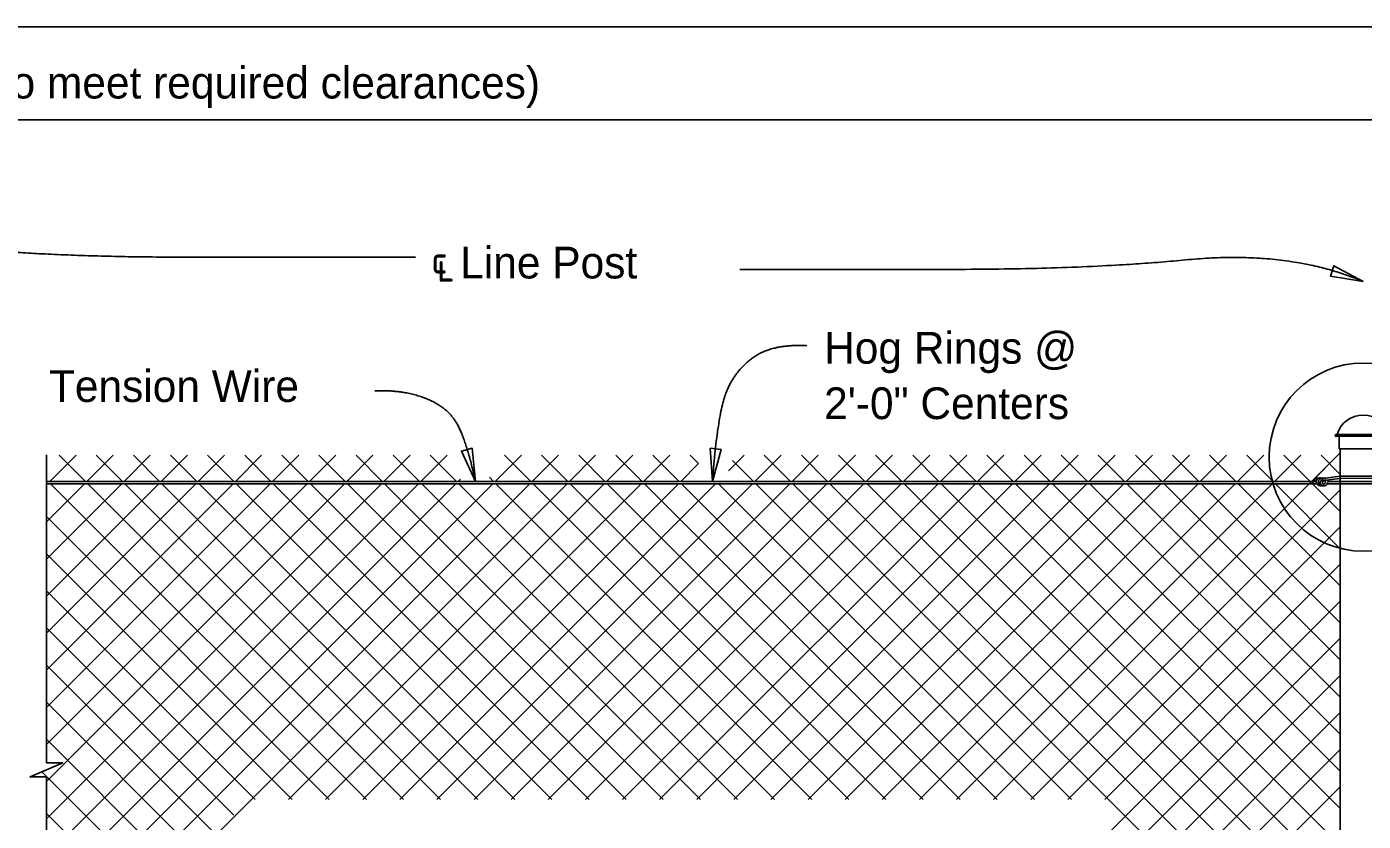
# Model space of a CAD drawing. Extents: x 0 to 41.1, y 0 to 25.9.
# Drawn here: x 16.13 to 24.62, y 20.9 to 25.95 of the extents above; entities that cross this region are included whole.
import ezdxf

# ---------------------------------------------------------------- set-up
doc = ezdxf.new("R2010")
doc.units = 0
for name, color, linetype in [('ActivePts-ConstElements', 7, 'Continuous'), ('Dimension', 7, 'Continuous'), ('Miscellaneous', 7, 'Continuous'), ('Miscellaneous1', 7, 'Continuous'), ('SteelMisc', 7, 'Continuous'), ('SteelMisc_h', 7, 'Continuous'), ('TextStructures', 7, 'Continuous')]:
    doc.layers.add(name, color=color, linetype=linetype)

msp = doc.modelspace()

# ---------------------------------------------------------------- linework, layer by layer
at = {"layer": 'ActivePts-ConstElements'}
msp.add_lwpolyline([(0, 0), (41.0506, 0), (41.0506, 25.9461), (0, 25.9461)], close=True, dxfattribs=at)
at = {"layer": 'Dimension'}
for points in [[(13.615, 25.3556), (15.0787, 25.3556), (15.0787, 25.4589), (15.1237, 25.3556), (15.1687, 25.2523), (15.1687, 25.3556), (28.4596, 25.3556)], [(16.252, 23.2265), (16.252, 21.2702), (16.3553, 21.2702), (16.252, 21.2252), (16.1487, 21.1802), (16.252, 21.1802), (16.252, 20.2867)]]:
    msp.add_lwpolyline(points, dxfattribs=at)
for points in [[(24.6151, 24.3284), (24.4287, 24.4277), (24.4064, 24.3608)], [(18.9764, 23.0579), (18.9562, 23.2681), (18.8881, 23.2497)], [(20.4816, 23.0579), (20.5377, 23.2615), (20.4675, 23.2686)]]:
    msp.add_lwpolyline(points, close=True, dxfattribs=at)
msp.add_circle((24.615, 23.212), 0.5976, dxfattribs=at)
for points in [[(18.5966, 24.4827), (17.7933, 24.4827), (16.4039, 24.4827), (15.2225, 24.5773), (14.615, 24.6814)], [(20.6562, 24.4046), (21.1029, 24.4046), (22.8703, 24.4046), (24.1369, 24.5276), (24.615, 24.3283)], [(21.0813, 23.9198), (20.8634, 23.9322), (20.6196, 23.7577), (20.5135, 23.4738), (20.4817, 23.0578)], [(18.338, 23.6332), (18.5184, 23.6403), (18.8013, 23.5305), (18.9216, 23.311), (18.9764, 23.0578)]]:
    msp.add_open_spline(points, degree=2, dxfattribs=at)
at = {"layer": 'Miscellaneous'}
for p, q in [((16.2736, 23.0578), (16.4402, 23.2245)), ((16.3328, 23.2245), (16.4994, 23.0578)), ((16.5093, 23.0578), (16.6759, 23.2245)), ((16.5685, 23.2245), (16.7352, 23.0578)), ((16.745, 23.0578), (16.9116, 23.2245)), ((16.8042, 23.2245), (16.9709, 23.0578)), ((16.9807, 23.0578), (17.1473, 23.2245)), ((17.0399, 23.2245), (17.2066, 23.0578)), ((17.2164, 23.0578), (17.383, 23.2245)), ((17.2756, 23.2245), (17.4423, 23.0578)), ((17.4521, 23.0578), (17.6187, 23.2245)), ((17.5113, 23.2245), (17.678, 23.0578)), ((17.6878, 23.0578), (17.8544, 23.2245)), ((17.747, 23.2245), (17.9137, 23.0578)), ((17.9235, 23.0578), (18.0901, 23.2245)), ((17.9827, 23.2245), (18.1494, 23.0578)), ((18.1592, 23.0578), (18.3258, 23.2245)), ((18.2184, 23.2245), (18.3851, 23.0578)), ((18.3949, 23.0578), (18.5615, 23.2245)), ((18.4541, 23.2245), (18.6208, 23.0578)), ((18.6306, 23.0578), (18.7972, 23.2245)), ((18.6898, 23.2245), (18.8565, 23.0578)), ((19.102, 23.0578), (19.2687, 23.2245)), ((19.1612, 23.2245), (19.3279, 23.0578)), ((19.3377, 23.0578), (19.5044, 23.2245)), ((19.3969, 23.2245), (19.5636, 23.0578)), ((19.5734, 23.0578), (19.7401, 23.2245)), ((19.6326, 23.2245), (19.7993, 23.0578)), ((19.8091, 23.0578), (19.9758, 23.2245)), ((19.8683, 23.2245), (20.035, 23.0578)), ((20.0448, 23.0578), (20.2115, 23.2245)), ((20.104, 23.2245), (20.2707, 23.0578)), ((20.3397, 23.2245), (20.3934, 23.1708)), ((20.5829, 23.1245), (20.6829, 23.2245)), ((20.6086, 23.1914), (20.7421, 23.0578)), ((20.7519, 23.0578), (20.9186, 23.2245)), ((20.8111, 23.2245), (20.9778, 23.0578)), ((20.9876, 23.0578), (21.1543, 23.2245)), ((21.0468, 23.2245), (21.2135, 23.0578)), ((21.2233, 23.0578), (21.39, 23.2245)), ((21.2825, 23.2245), (21.4492, 23.0578)), ((21.459, 23.0578), (21.6257, 23.2245)), ((21.5182, 23.2245), (21.6849, 23.0578)), ((21.6947, 23.0578), (21.8614, 23.2245)), ((21.7539, 23.2245), (21.9206, 23.0578)), ((21.9304, 23.0578), (22.0971, 23.2245)), ((21.9896, 23.2245), (22.1563, 23.0578)), ((22.1661, 23.0578), (22.3328, 23.2245)), ((22.2253, 23.2245), (22.392, 23.0578)), ((22.2674, 21.0378), (24.4692, 23.2396)), ((22.4018, 23.0578), (22.5685, 23.2245)), ((22.461, 23.2245), (22.6277, 23.0578)), ((22.6375, 23.0578), (22.8042, 23.2245)), ((22.6967, 23.2245), (22.8634, 23.0578)), ((22.8732, 23.0578), (23.0399, 23.2245)), ((22.9324, 23.2245), (23.0991, 23.0578)), ((23.1089, 23.0578), (23.2756, 23.2245)), ((23.1681, 23.2245), (23.3348, 23.0578)), ((23.3446, 23.0578), (23.5113, 23.2245)), ((23.4038, 23.2245), (23.5705, 23.0578)), ((23.5803, 23.0578), (23.747, 23.2245)), ((23.6396, 23.2245), (23.8062, 23.0578)), ((23.816, 23.0578), (23.9827, 23.2245)), ((23.8753, 23.2245), (24.0419, 23.0578)), ((24.0517, 23.0578), (24.2184, 23.2245)), ((24.111, 23.2245), (24.2776, 23.0578)), ((24.2874, 23.0578), (24.4541, 23.2245)), ((24.3467, 23.2245), (24.4692, 23.1019)), ((20.2805, 23.0578), (20.3934, 23.1708)), ((16.252, 19.7364), (19.5586, 23.0431)), ((16.252, 20.2078), (19.0872, 23.0431)), ((16.252, 21.1506), (18.1444, 23.0431)), ((16.252, 20.6792), (18.6158, 23.0431)), ((16.252, 19.9721), (19.3229, 23.0431)), ((16.252, 20.4435), (18.8515, 23.0431)), ((16.252, 20.9149), (18.3801, 23.0431)), ((16.252, 21.3863), (17.9087, 23.0431)), ((16.252, 21.622), (17.673, 23.0431)), ((16.252, 22.0934), (17.2016, 23.0431)), ((16.252, 21.8577), (17.4373, 23.0431)), ((16.252, 22.5648), (16.7302, 23.0431)), ((16.252, 23.0363), (16.2588, 23.0431)), ((16.252, 22.3291), (16.9659, 23.0431)), ((16.252, 22.8005), (16.4945, 23.0431)), ((16.2785, 23.0431), (18.2838, 21.0378)), ((16.5142, 23.0431), (18.5195, 21.0378)), ((16.7499, 23.0431), (18.7552, 21.0378)), ((16.9856, 23.0431), (18.9909, 21.0378)), ((17.2213, 23.0431), (19.2266, 21.0378)), ((17.457, 23.0431), (19.4623, 21.0378)), ((17.6927, 23.0431), (19.698, 21.0378)), ((17.7891, 21.0378), (19.7943, 23.0431)), ((17.9284, 23.0431), (19.9337, 21.0378)), ((18.0248, 21.0378), (20.03, 23.0431)), ((18.1641, 23.0431), (20.1694, 21.0378)), ((18.2605, 21.0378), (20.2657, 23.0431)), ((18.3998, 23.0431), (20.4051, 21.0378)), ((18.4962, 21.0378), (20.5014, 23.0431)), ((18.6355, 23.0431), (20.6408, 21.0378)), ((18.7319, 21.0378), (20.7372, 23.0431)), ((18.8663, 23.0578), (18.8813, 23.0728)), ((18.8712, 23.0431), (20.8765, 21.0378)), ((18.9676, 21.0378), (20.9729, 23.0431)), ((19.065, 23.085), (19.0922, 23.0578)), ((19.1069, 23.0431), (21.1122, 21.0378)), ((19.2033, 21.0378), (21.2086, 23.0431)), ((19.3426, 23.0431), (21.3479, 21.0378)), ((19.439, 21.0378), (21.4443, 23.0431)), ((19.5783, 23.0431), (21.5836, 21.0378)), ((19.6747, 21.0378), (21.68, 23.0431)), ((19.814, 23.0431), (21.8193, 21.0378)), ((19.9104, 21.0378), (21.9157, 23.0431)), ((20.0497, 23.0431), (22.055, 21.0378)), ((20.1461, 21.0378), (22.1514, 23.0431)), ((20.2854, 23.0431), (22.2907, 21.0378)), ((20.3818, 21.0378), (22.3871, 23.0431)), ((20.5211, 23.0431), (22.5264, 21.0378)), ((20.6175, 21.0378), (22.6228, 23.0431)), ((20.7568, 23.0431), (22.7621, 21.0378)), ((20.8532, 21.0378), (22.8585, 23.0431)), ((20.9925, 23.0431), (24.4692, 19.5664)), ((21.0889, 21.0378), (23.0942, 23.0431)), ((21.2282, 23.0431), (24.4692, 19.8021)), ((21.3246, 21.0378), (23.3299, 23.0431)), ((21.4639, 23.0431), (24.4692, 20.0378)), ((21.5603, 21.0378), (23.5656, 23.0431)), ((21.6996, 23.0431), (24.4692, 20.2735)), ((21.796, 21.0378), (23.8013, 23.0431)), ((21.9353, 23.0431), (24.4692, 20.5092)), ((22.0317, 21.0378), (24.037, 23.0431)), ((22.1711, 23.0431), (24.4692, 20.7449)), ((22.4068, 23.0431), (24.4692, 20.9806)), ((22.5031, 21.0378), (24.4692, 23.0039)), ((22.6425, 23.0431), (24.4692, 21.2163)), ((22.8782, 23.0431), (24.4692, 21.452)), ((23.1139, 23.0431), (24.4692, 21.6877)), ((23.3496, 23.0431), (24.4692, 21.9234)), ((23.5853, 23.0431), (24.4692, 22.1591)), ((23.821, 23.0431), (24.4692, 22.3948)), ((24.0567, 23.0431), (24.4692, 22.6305)), ((24.2924, 23.0431), (24.4692, 22.8662)), ((16.252, 22.8339), (18.0481, 21.0378)), ((22.7388, 21.0378), (24.4692, 22.7682)), ((16.252, 22.5982), (17.8124, 21.0378)), ((22.9745, 21.0378), (24.4692, 22.5325)), ((16.252, 22.3625), (17.5767, 21.0378)), ((22.9985, 20.8261), (24.4692, 22.2968)), ((16.252, 22.1268), (17.4417, 20.9371)), ((22.9985, 20.5904), (24.4692, 22.0611)), ((16.252, 21.8911), (17.4417, 20.7014)), ((22.9985, 20.3547), (24.4692, 21.8254)), ((16.252, 21.6554), (17.4417, 20.4657)), ((22.9985, 20.119), (24.4692, 21.5897)), ((16.252, 21.4197), (17.4417, 20.23)), ((21.9677, 18.8525), (24.4692, 21.354)), ((16.2232, 21.2127), (17.4417, 19.9943)), ((22.2034, 18.8525), (24.4692, 21.1183)), ((16.252, 20.9483), (19.7943, 17.4059))]:
    msp.add_line(p, q, dxfattribs=at)
at = {"layer": 'Miscellaneous1'}
msp.add_lwpolyline([(0, 25.9461), (41.0506, 25.9461), (41.0506, 0), (0, 0)], close=True, dxfattribs=at)
at = {"layer": 'SteelMisc'}
for p, q in [((24.4427, 23.3564), (24.7873, 23.3564)), ((24.7873, 23.3442), (24.4427, 23.3442)), ((24.461, 23.2645), (24.461, 23.3442)), ((24.7691, 23.2645), (24.461, 23.2645)), ((24.4692, 16.8894), (24.4692, 23.2644)), ((24.4692, 23.0904), (24.3743, 23.0793)), ((24.4692, 23.0904), (24.7604, 23.0921)), ((16.252, 23.0578), (24.2941, 23.0578)), ((16.252, 23.0431), (24.3207, 23.0431)), ((24.304, 23.0578), (24.3172, 23.0578)), ((24.4692, 23.0759), (24.3766, 23.0664)), ((24.3856, 23.0431), (24.4692, 23.0431)), ((24.387, 23.0578), (24.4692, 23.0578)), ((24.4692, 23.0759), (24.7604, 23.0776))]:
    msp.add_line(p, q, dxfattribs=at)
msp.add_arc((24.4429, 23.3502), 0.00613, 91.1647, 268.8353, dxfattribs=at)
for centre, major_axis, ratio, start_param, end_param in [((24.6157, 23.3154), (0.1711, 0), 0.957868, 0.252602, 2.888574), ((24.3283, 23.0436), (0.0373, 0), 0.957868, 1.486836, 3.108042), ((24.3494, 23.0039), (-0.0724, 0), 0.957868, 5.162149, 5.652106), ((24.3419, 23.0555), (-0.0249, 0), 0.957868, 6.009018, 7.089857), ((24.3408, 23.058), (0.023, 0), 0.957868, 1.29026, 2.970541), ((24.3433, 23.0515), (0.0231, 0), 0.957868, 3.779554, 4.879821), ((24.3595, 23.0527), (0.0295, 0), 0.957868, 1.220941, 4.039556), ((24.373, 23.0544), (-0.0303, -0.0108), 0.724765, 4.35367, 6.324556), ((24.3494, 23.0458), (0.0206, -0.0021), 0.798607, 4.32653, 5.220153), ((24.3629, 23.0458), (0.0206, -0.0021), 0.798607, 3.333154, 5.220153), ((24.3697, 23.0504), (-0.0139, 0), 0.957868, 5.22362, 6.905413), ((24.364, 23.048), (-0.00795, 0), 0.957868, 6.140374, 9.314262), ((24.3781, 23.0415), (-0.0259, 0), 0.957868, 4.777514, 5.62749), ((24.3624, 23.0538), (0.0119, 0), 0.957868, 5.725876, 7.416677), ((24.3555, 23.0646), (0.0391, 0), 0.957868, 5.082588, 5.41974), ((24.3624, 23.0538), (0.0119, 0), 0.957868, 5.639684, 5.723117), ((24.3626, 23.0525), (0.0251, 0), 0.957868, 5.531357, 6.227833), ((24.3626, 23.0525), (0.0251, 0), 0.957868, 0.407687, 0.609214)]:
    msp.add_ellipse(centre, major_axis=major_axis, ratio=ratio, start_param=start_param, end_param=end_param, dxfattribs=at)
at = {"layer": 'SteelMisc_h'}
for p, q in [((24.4692, 23.0578), (24.7609, 23.0578)), ((24.4692, 23.0431), (24.7609, 23.0431))]:
    msp.add_line(p, q, dxfattribs=at)

# ---------------------------------------------------------------- texts
at = {"layer": 'Dimension'}
for s, p in [('Hog Rings @ ', (21.1911, 23.8055)), ('2\'-0" Centers', (21.1911, 23.4535))]:
    msp.add_text(s, height=0.2016, dxfattribs=at).set_placement(p)
at = {"layer": 'TextStructures'}
for s, p in [('Equal Spaces @ 10\'-0" Max. (Posts may be shifted minimally to meet required clearances)', (8.5826, 25.4902)), ('℄ Line Post', (18.6958, 24.347)), ('Tension Wire', (16.268, 23.5627))]:
    msp.add_text(s, height=0.2016, dxfattribs=at).set_placement(p)

doc.saveas('drawing.dxf')
